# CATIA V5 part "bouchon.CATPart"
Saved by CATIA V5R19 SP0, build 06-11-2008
Part number: bouchon
Bounding box of the stored display mesh (mm): x 0 to 8.112, y -4 to 4, z -4 to 4
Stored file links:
  G:\project guitar elect\bouchon.CATPart
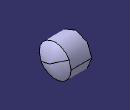
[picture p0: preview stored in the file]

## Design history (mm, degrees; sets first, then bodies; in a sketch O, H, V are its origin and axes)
Body1 (main body)
  Sketch1 on yz-plane, origin (0, 0, 0), H (0, 1, 0), V (0, 0, 1)
    circle A1 centre (0, 0) radius 1.6
    radius A1 = 1.6
  Pad1: profile Sketch1, direction (1, 0, 0), length 1.5
  Sketch2 on end face of Pad1, origin (1.5, 0, 0), H (0, 1, 0), V (0, 0, 1)
    circle A1 centre (0, 0) radius 4
    radius A1 = 4
  Pad2: profile Sketch2, direction (1, 0, 0), length 5.176
  Sketch3 on xy-plane, origin (0, 0, 0), H (1, 0, 0), V (0, 1, 0)
    point P1 (6.676, 4)
    arc A1 centre (1.4088, -0.1494) radius 6.7053 from (6.676, 4) to (8.1124, 0) cw
    point P3 (8.1124, 0)
    line L1 (6.676, 4) -> (6.676, 0)
    point P4 (6.676, 0)
    line L2 (6.676, 0) -> (8.1124, 0)
    reference projected line E1 (6.676, 4) -> (6.676, -4) from edge [face of Pad2 from Sketch2.A1 | end face of Pad2]
    reference projected line E2 through (0, 0) direction (1, 0) from axis of face of Pad2 from Sketch2.A1
    distance L1 E1 = 0
    distance P1 E2 = 4
    coincidence: P3 H, P4 H
    vertical: L1 V
    horizontal: L2 H
  Shaft1: profile Sketch3, axis Sketch3.L2, angle 360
